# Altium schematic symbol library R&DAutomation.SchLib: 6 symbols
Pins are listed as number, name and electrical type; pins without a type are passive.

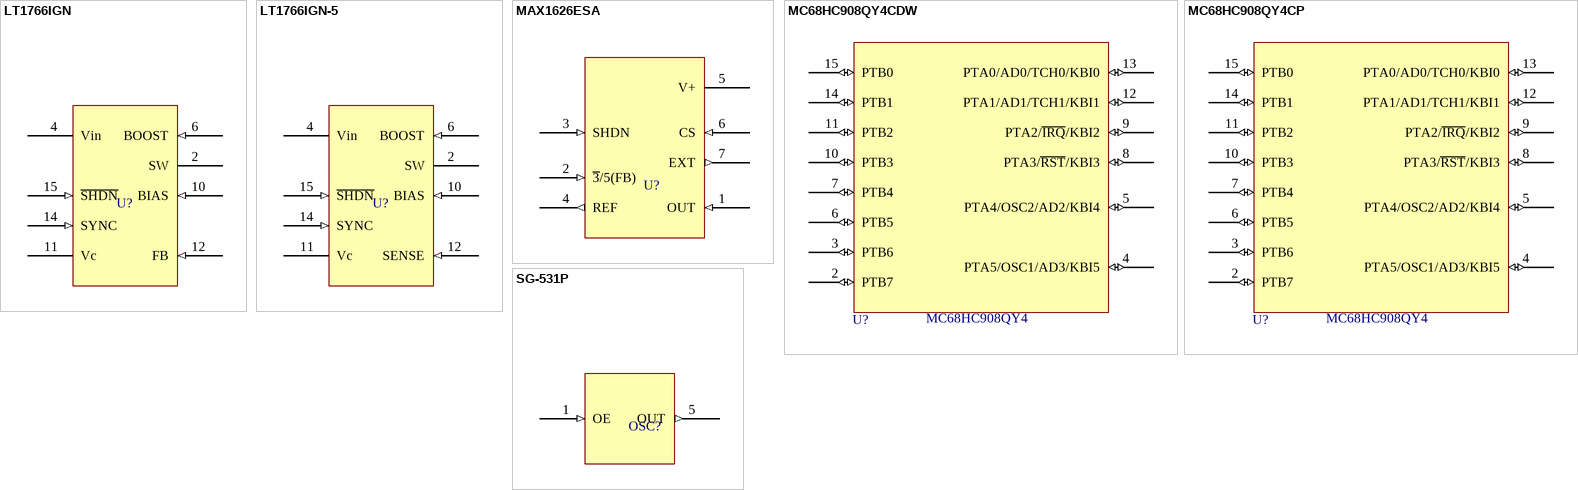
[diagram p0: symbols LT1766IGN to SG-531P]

## LT1766IGN
designator U?
High Voltage 1.5A, 200kHz Step-Down Switching Regulator; Manufacturer: Linear Technologies; CLASS I: Power Management; CLASS II: DC-DC Converter
footprint SSO-G16
pins: 1 GND (power) hidden to GND, 2 SW (oe), 4 Vin (power), 6 BOOST (in), 8 GND (power) hidden to GND, 9 GND (power) hidden to GND, 10 BIAS (in), 11 Vc (power), 12 FB (in), 14 SYNC (in), 15 ~{SHDN} (in), 16 GND (power) hidden to GND

## LT1766IGN-5
designator U?
High Voltage 1.5A, 200kHz Step-Down Switching Regulator Fixed 5v Out; Manufacturer: Linear Technologies; CLASS I: Power Management; CLASS II: DC-DC Converter
footprint SSO-G16
pins: 1 GND (power) hidden to GND, 2 SW (oe), 4 Vin (power), 6 BOOST (in), 8 GND (power) hidden to GND, 9 GND (power) hidden to GND, 10 BIAS (in), 11 Vc (power), 12 SENSE (in), 14 SYNC (in), 15 ~{SHDN} (in), 16 GND (power) hidden to GND

## MAX1626ESA
designator U?
5V/3.3V or Adjustable, High-Efficiency, Step-Down DC-DC Controller; Manufacturer: Maxim; CLASS I: Power Management; CLASS II: DC-DC Converter
footprint SOP8
pins: 1 OUT (in) "Output Sense Input", 2 ~{3}/5(FB) (in), 3 SHDN (in), 4 REF (out), 5 V+ (power), 6 CS (in), 7 EXT (out), 8 GND (power) hidden to GND

## MC68HC908QY4CDW
designator U?, comment MC68HC908QY4
Flash based 8 Bit HC08 Microcontroller; Manufacturer: Motorola; CLASS II: 8 bit
footprint SO-G16/D10
pins: 1 Vdd (power) hidden to VCC, 2 PTB7 (io) "Port B7", 3 PTB6 (io) "Port B6", 4 PTA5/OSC1/AD3/KBI5 (io) "Port A5", 5 PTA4/OSC2/AD2/KBI4 (io) "Port A4", 6 PTB5 (io) "Port B5", 7 PTB4 (io) "Port B4", 8 PTA3/~{RST}/KBI3 (io) "Port A3", 9 PTA2/~{IRQ}/KBI2 (io) "Port A2", 10 PTB3 (io) "Port B3", 11 PTB2 (io) "Port B2", 12 PTA1/AD1/TCH1/KBI1 (io) "Port A1", 13 PTA0/AD0/TCH0/KBI0 (io) "Port A0", 14 PTB1 (io) "Port B1", 15 PTB0 (io) "Port B0", 16 Vss (power) hidden to GND

## MC68HC908QY4CP
designator U?, comment MC68HC908QY4
Flash based 8 Bit HC08 Microcontroller; Manufacturer: Motorola; CLASS II: 8 bit
footprint DIP-P16
pins: 1 Vdd (power) hidden to VCC, 2 PTB7 (io) "Port B7", 3 PTB6 (io) "Port B6", 4 PTA5/OSC1/AD3/KBI5 (io) "Port A5", 5 PTA4/OSC2/AD2/KBI4 (io) "Port A4", 6 PTB5 (io) "Port B5", 7 PTB4 (io) "Port B4", 8 PTA3/~{RST}/KBI3 (io) "Port A3", 9 PTA2/~{IRQ}/KBI2 (io) "Port A2", 10 PTB3 (io) "Port B3", 11 PTB2 (io) "Port B2", 12 PTA1/AD1/TCH1/KBI1 (io) "Port A1", 13 PTA0/AD0/TCH0/KBI0 (io) "Port A0", 14 PTB1 (io) "Port B1", 15 PTB0 (io) "Port B0", 16 Vss (power) hidden to GND

## SG-531P
designator OSC?
Half size DIP high freq. crystal oscillator; Manufacturer: Epson
footprint DIP-P4
pins: 1 OE (in), 4 GND (power) hidden to GND, 5 OUT (out), 8 Vdd (power) hidden to VCC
